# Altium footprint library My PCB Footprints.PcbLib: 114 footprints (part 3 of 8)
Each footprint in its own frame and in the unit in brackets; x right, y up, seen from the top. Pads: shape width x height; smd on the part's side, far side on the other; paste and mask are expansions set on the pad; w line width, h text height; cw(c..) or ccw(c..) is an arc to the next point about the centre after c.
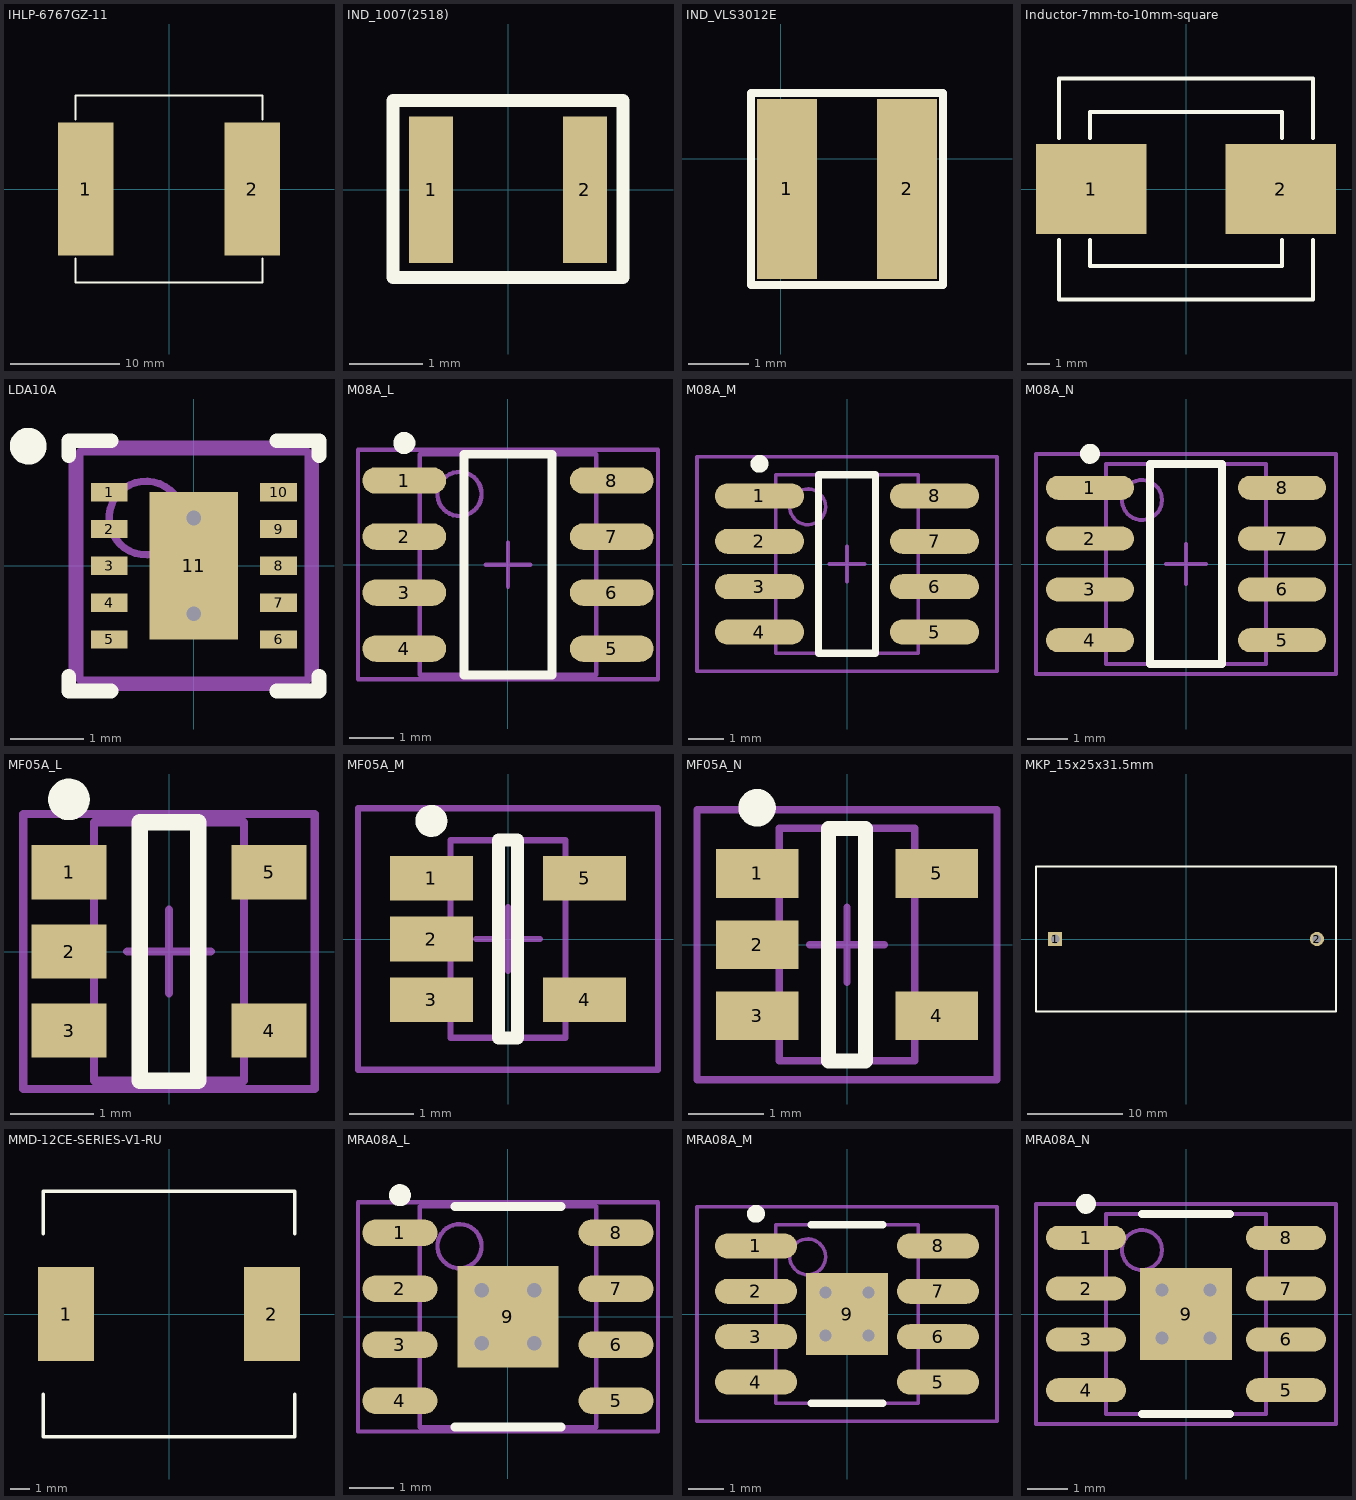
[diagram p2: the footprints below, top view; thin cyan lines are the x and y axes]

## IHLP-6767GZ-11 [mil] "Vishay Dale land pattern with wider pad.  Document 34282 rev 30-Aug-10"
height 276
pads (2):
  rect 200x480 smd: 1(-301,0) 2(301,0)
Top Overlay:
  lines w7: -337.5,-250 -337.5,-337.5 0,-337.5 ; -337.5,250 -337.5,337.5 0,337.5 337.5,337.5 337.5,250 ; 0,-337.3 337.5,-337.5 337.5,-250
Mechanical 5:
  text ".Designator" at -60,-20 h40
3D body: height 276, standoff 0, extent -337.5,-337.31 337.5,337.5

## IND_1007(2518) [mm] "Footprint for 1007 (2518 metric) inductor, Taiyo Yuden BRC2518T series"
height 1.8
pads (2):
  rect 0.6x2 smd: 1(-1.05,0) 2(1.05,0)
Top Overlay:
  lines w0.178: -1.575,-1.2 1.575,-1.2 1.575,1.225 -1.575,1.225 -1.575,-1.2
Mechanical 5:
  text ".Designator" at -0.1,-0.1 h1.02
3D body: height 1.8, standoff 0, extent -1.6,-1.225 1.6,1.2

## IND_VLS3012E [mm] "TDK VLS3012E Type Inductor footprint"
height 1.2
pads (2):
  rect 1x3 smd: 1(0.1,-0.5) 2(2.1,-0.5)
Top Overlay:
  lines w0.127: -0.5,-2.1 -0.5,1.1 2.7,1.1 2.7,-2.1 -0.5,-2.1
Mechanical 5:
  text ".Designator" at -1.524,-0.508 h1.02
3D body: height 1.2, standoff 0, extent -0.7,-2.1 2.7,1.2

## Inductor-7mm-to-10mm-square [mm] "Custom land pattern"
height 3
pads (2):
  rect 5x4.1 smd: 1(-4.3,0) 2(4.3,0)
Top Overlay:
  lines w0.178: -5.75,-2.3 -5.75,-5 0,-5 5.75,-5 5.75,-2.3 ; -5.75,2.3 -5.75,5 0,5 5.75,5 5.75,2.3 ; -4.35,-2.3 -4.35,-3.5 4.35,-3.5 4.35,-2.3 ; -4.35,2.3 -4.35,3.5 4.35,3.5 4.35,2.3
Mechanical 5:
  text ".Designator" at -1.524,-0.508 h1.02
3D body: height 3, standoff 0, extent -5.75,-5 5.75,5

## LDA10A [mm] "PSON, 10-Leads, Body 3x3mm, Pitch 0.5mm, NSC Recommended"
height 0.8
pads (11):
  rect 0.5x0.25 smd paste-0.125 mask+0.051: 1(-1.15,1) 2(-1.15,0.5) 3(-1.15,0) 4(-1.15,-0.5) 5(-1.15,-1) 6(1.15,-1) 7(1.15,-0.5) 8(1.15,0) 9(1.15,0.5) 10(1.15,1)
  rect 1.2x2 smd paste-0.6 mask+0.051: 11(0,0)
via 0,-0.65 diameter 0.5 hole 0.2
via 0,0.65 diameter 0.5 hole 0.2
Top Overlay:
  circle w0.25: c-2.25,1.625 r0.125
  lines w0.2: -1.7,-1.5 -1.7,-1.7 -1.125,-1.7 ; -1.7,1.5 -1.7,1.7 -1.125,1.7 ; 1.125,-1.7 1.7,-1.7 1.7,-1.5 ; 1.125,1.7 1.7,1.7 1.7,1.5
Top Paste:
  region: 1.5,-0.875 1,-0.875 1,-1.125 1.5,-1.125
  region: 1.5,-0.375 1,-0.375 1,-0.625 1.5,-0.625
  region: 1.5,0.125 1,0.125 1,-0.125 1.5,-0.125
  region: 1.5,0.625 1,0.625 1,0.375 1.5,0.375
  region: 1.5,1.125 1,1.125 1,0.875 1.5,0.875
  rectangle: -1.5,-1.125 -1,-0.875
  rectangle: -1.5,-0.625 -1,-0.375
  rectangle: -1.5,-0.125 -1,0.125
  rectangle: -1.5,0.375 -1,0.625
  rectangle: -1.5,0.875 -1,1.125
  rectangle: -0.57,-0.95 0.57,0.95
Mechanical 5:
  text ".Designator" at -1.524,-0.508 h1.02
Mechanical 13:
  circle w0.1: c-0.65,0.65 r0.5
  lines w0.1: -1.55,-1.55 1.55,-1.55 1.55,1.55 -1.55,1.55 -1.55,-1.55
Mechanical 15:
  lines w0.1: -0.5,0 0.5,0 ; 0,-0.5 0,0.5 ; -1.65,-1.65 1.65,-1.65 1.65,1.65 -1.65,1.65 -1.65,-1.65
3D body: height 0.8, standoff 0, extent -1.55,-1.55 1.55,1.55

## M08A_L [mm] "SOIC, 8-Leads, Body 4.9x3.9mm, Pitch 1.27mm, IPC High Density"
height 1.75
pads (8):
  oval 1.9x0.6 smd: 1(-2.35,1.905) 2(-2.35,0.635) 3(-2.35,-0.635) 4(-2.35,-1.905) 5(2.35,-1.905) 6(2.35,-0.635) 7(2.35,0.635) 8(2.35,1.905)
Top Overlay:
  circle w0.25: c-2.35,2.755 r0.125
  lines w0.2: -1,-2.5 1,-2.5 1,2.5 -1,2.5 -1,-2.5
Mechanical 5:
  text ".Designator" at -1.524,-0.508 h1.02
Mechanical 13:
  circle w0.1: c-1.1,1.6 r0.5
  lines w0.1: -2,-2.5 2,-2.5 2,2.5 -2,2.5 -2,-2.5
Mechanical 15:
  lines w0.1: -0.5,0 0.5,0 ; 0,-0.5 0,0.5 ; -3.4,-2.6 3.4,-2.6 3.4,2.6 -3.4,2.6 -3.4,-2.6
3D body: height 1.75, standoff 0, extent -2,-2.5 2,2.5

## M08A_M [mm] "SOIC, 8-Leads, Body 4.9x3.9mm, Pitch 1.27mm, IPC Low Density"
height 1.75
pads (8):
  oval 2.5x0.7 smd: 1(-2.45,1.905) 2(-2.45,0.635) 3(-2.45,-0.635) 4(-2.45,-1.905) 5(2.45,-1.905) 6(2.45,-0.635) 7(2.45,0.635) 8(2.45,1.905)
Top Overlay:
  circle w0.25: c-2.45,2.805 r0.125
  lines w0.2: -0.8,-2.5 -0.8,2.5 0.8,2.5 0.8,-2.5 -0.8,-2.5
Mechanical 5:
  text ".Designator" at -1.524,-0.508 h1.02
Mechanical 13:
  circle w0.1: c-1.1,1.6 r0.5
  lines w0.1: -2,-2.5 -2,2.5 2,2.5 2,-2.5 -2,-2.5
Mechanical 15:
  lines w0.1: -0.5,0 0.5,0 ; 0,-0.5 0,0.5 ; -4.2,-3 -4.2,3 4.2,3 4.2,-3 -4.2,-3
3D body: height 1.75, standoff 0, extent -2,-2.5 2,2.5

## M08A_N [mm] "SOIC, 8-Leads, Body 4.9x3.9mm, Pitch 1.27mm, IPC Medium Density"
height 1.75
pads (8):
  oval 2.2x0.6 smd: 1(-2.4,1.905) 2(-2.4,0.635) 3(-2.4,-0.635) 4(-2.4,-1.905) 5(2.4,-1.905) 6(2.4,-0.635) 7(2.4,0.635) 8(2.4,1.905)
Top Overlay:
  circle w0.25: c-2.4,2.755 r0.125
  lines w0.2: -0.9,-2.5 -0.9,2.5 0.9,2.5 0.9,-2.5 -0.9,-2.5
Mechanical 5:
  text ".Designator" at -1.524,-0.508 h1.02
Mechanical 13:
  circle w0.1: c-1.1,1.6 r0.5
  lines w0.1: -2,-2.5 -2,2.5 2,2.5 2,-2.5 -2,-2.5
Mechanical 15:
  lines w0.1: -0.5,0 0.5,0 ; 0,-0.5 0,0.5 ; -3.75,-2.75 -3.75,2.75 3.75,2.75 3.75,-2.75 -3.75,-2.75
3D body: height 1.75, standoff 0, extent -2,-2.5 2,2.5

## MF05A_L [mm] "SOT23, 5-Leads, Body 2.9x1.6mm, Pitch 0.95mm, Lead Span 2.8mm, IPC High Density"
height 1.19
pads (5):
  rect 0.9x0.65 smd: 1(-1.2,0.95) 2(-1.2,0) 3(-1.2,-0.95) 4(1.2,-0.95) 5(1.2,0.95)
Top Overlay:
  circle w0.25: c-1.2,1.825 r0.125
  lines w0.2: -0.35,-1.55 -0.35,1.55 0.35,1.55 0.35,-1.55 -0.35,-1.55
Mechanical 5:
  text ".Designator" at -1.524,-0.508 h1.02
Mechanical 13:
  lines w0.1: -0.9,-1.55 0.9,-1.55 0.9,1.55 -0.9,1.55 -0.9,-1.55
Mechanical 15:
  lines w0.1: -0.5,0 0.5,0 ; 0,-0.5 0,0.5 ; -1.75,-1.65 1.75,-1.65 1.75,1.65 -1.75,1.65 -1.75,-1.65
3D body: height 1.19, standoff 0, extent -0.9,-1.55 0.9,1.55

## MF05A_M [mm] "SOT23, 5-Leads, Body 2.9x1.6mm, Pitch 0.95mm, Lead Span 2.8mm, IPC Low Density"
height 1.19
pads (5):
  rect 1.3x0.7 smd: 1(-1.2,0.95) 2(-1.2,0) 3(-1.2,-0.95) 4(1.2,-0.95) 5(1.2,0.95)
Top Overlay:
  circle w0.25: c-1.2,1.85 r0.125
  lines w0.2: -0.15,-1.55 -0.15,1.55 0.15,1.55 0.15,-1.55 -0.15,-1.55
Mechanical 5:
  text ".Designator" at -1.524,-0.508 h1.02
Mechanical 13:
  lines w0.1: -0.9,-1.55 0.9,-1.55 0.9,1.55 -0.9,1.55 -0.9,-1.55
Mechanical 15:
  lines w0.1: -0.5,0 0.5,0 ; 0,-0.5 0,0.5 ; -2.35,-2.05 2.35,-2.05 2.35,2.05 -2.35,2.05 -2.35,-2.05
3D body: height 1.19, standoff 0, extent -0.9,-1.55 0.9,1.55

## MF05A_N [mm] "SOT23, 5-Leads, Body 2.9x1.6mm, Pitch 0.95mm, Lead Span 2.8mm, IPC Medium Density"
height 1.19
pads (5):
  rect 1.1x0.65 smd: 1(-1.2,0.95) 2(-1.2,0) 3(-1.2,-0.95) 4(1.2,-0.95) 5(1.2,0.95)
Top Overlay:
  circle w0.25: c-1.2,1.825 r0.125
  lines w0.2: -0.25,-1.55 -0.25,1.55 0.25,1.55 0.25,-1.55 -0.25,-1.55
Mechanical 5:
  text ".Designator" at -1.524,-0.508 h1.02
Mechanical 13:
  lines w0.1: -0.9,-1.55 0.9,-1.55 0.9,1.55 -0.9,1.55 -0.9,-1.55
Mechanical 15:
  lines w0.1: -0.5,0 0.5,0 ; 0,-0.5 0,0.5 ; -2,-1.8 2,-1.8 2,1.8 -2,1.8 -2,-1.8
3D body: height 1.19, standoff 0, extent -0.9,-1.55 0.9,1.55

## MKP_15x25x31.5mm [mm] "Flm capacitors, 27.5mm spacing"
height 24.5
pads (2):
  rect 1.5x1.5 hole 0.9: 1(-13.75,0)
  round 1.5 hole 0.9: 2(13.75,0)
Top Overlay:
  lines w0.178: -15.75,-7.62 0.62,-7.62 15.75,-7.62 15.75,0 15.75,7.62 -0.396,7.62 -15.75,7.62 -15.75,0 -15.75,-7.62
Mechanical 5:
  text ".Designator" at -1.524,-0.508 h1.02
3D body: height 24.5, standoff 0, extent -15.749,-7.62 15.749,7.366

## MMD-12CE-SERIES-V1-RU [mm] "Mag.Layers land pattern"
height 3.5
pads (2):
  rect 2.95x4.95 smd: 1(-5.4,0) 2(5.4,0)
Top Overlay:
  lines w0.178: -6.6,-4.2 -6.6,-6.45 0,-6.45 6.6,-6.45 6.6,-4.2 ; -6.6,4.2 -6.6,6.45 0,6.45 6.6,6.45 6.6,4.2
Mechanical 5:
  text ".Designator" at -1.524,-0.508 h1.02
3D body: height 3.5, standoff 0, extent -6.6,-6.45 6.6,6.45

## MRA08A_L [mm] "SOIC, 8-Leads, Body 4.9x3.9mm, Pitch 1.27mm, Exposed Pad, IPC High Density"
height 1.68
pads (9):
  oval 1.7x0.6 smd: 1(-2.45,1.905) 2(-2.45,0.635) 3(-2.45,-0.635) 4(-2.45,-1.905) 5(2.45,-1.905) 6(2.45,-0.635) 7(2.45,0.635) 8(2.45,1.905)
  rect 2.29x2.29 smd: 9(0,0)
via -0.6,-0.6 diameter 0.66 hole 0.33
via 0.6,-0.6 diameter 0.66 hole 0.33
via 0.6,0.6 diameter 0.66 hole 0.33
via -0.6,0.6 diameter 0.66 hole 0.33
Top Overlay:
  circle w0.25: c-2.45,2.755 r0.125
  lines w0.2: -1.2,-2.5 1.2,-2.5 ; -1.2,2.5 1.2,2.5 ; -1.1,2.5 1.1,2.5
Mechanical 5:
  text ".Designator" at -1.524,-0.508 h1.02
Mechanical 13:
  circle w0.1: c-1.1,1.6 r0.5
  lines w0.1: -2,-2.5 -2,2.5 2,2.5 2,-2.5 -2,-2.5
Mechanical 15:
  lines w0.1: -3.4,-2.6 -3.4,2.6 3.4,2.6 3.4,-2.6 -3.4,-2.6 ; -0.5,0 0.5,0 -0.5,0 ; 0,-0.5 0,0.5 0,-0.5
3D body: height 1.68, standoff 0.03, extent -2,-2.5 2,2.5

## MRA08A_M [mm] "SOIC, 8-Leads, Body 4.9x3.9mm, Pitch 1.27mm, Exposed Pad, IPC Low Density"
height 1.68
pads (9):
  oval 2.3x0.7 smd: 1(-2.55,1.905) 2(-2.55,0.635) 3(-2.55,-0.635) 4(-2.55,-1.905) 5(2.55,-1.905) 6(2.55,-0.635) 7(2.55,0.635) 8(2.55,1.905)
  rect 2.29x2.29 smd: 9(0,0)
via -0.6,-0.6 diameter 0.66 hole 0.33
via 0.6,-0.6 diameter 0.66 hole 0.33
via 0.6,0.6 diameter 0.66 hole 0.33
via -0.6,0.6 diameter 0.66 hole 0.33
Top Overlay:
  circle w0.25: c-2.55,2.805 r0.125
  lines w0.2: -1,-2.5 1,-2.5 ; -1,2.5 1,2.5 -1,2.5
Mechanical 5:
  text ".Designator" at -1.524,-0.508 h1.02
Mechanical 13:
  circle w0.1: c-1.1,1.6 r0.5
  lines w0.1: -2,-2.5 -2,2.5 2,2.5 2,-2.5 -2,-2.5
Mechanical 15:
  lines w0.1: -4.2,-3 -4.2,3 4.2,3 4.2,-3 -4.2,-3 ; -0.5,0 0.5,0 -0.5,0 ; 0,-0.5 0,0.5 0,-0.5
3D body: height 1.68, standoff 0.03, extent -2,-2.5 2,2.5

## MRA08A_N [mm] "SOIC, 8-Leads, Body 4.9x3.9mm, Pitch 1.27mm, Exposed Pad, IPC Medium Density"
height 1.68
pads (9):
  oval 2x0.6 smd: 1(-2.5,1.905) 2(-2.5,0.635) 3(-2.5,-0.635) 4(-2.5,-1.905) 5(2.5,-1.905) 6(2.5,-0.635) 7(2.5,0.635) 8(2.5,1.905)
  rect 2.29x2.29 smd: 9(0,0)
via -0.6,-0.6 diameter 0.66 hole 0.33
via 0.6,-0.6 diameter 0.66 hole 0.33
via 0.6,0.6 diameter 0.66 hole 0.33
via -0.6,0.6 diameter 0.66 hole 0.33
Top Overlay:
  circle w0.25: c-2.5,2.755 r0.125
  lines w0.2: -1.1,-2.5 1.1,-2.5 ; -1.1,2.5 1.1,2.5
Mechanical 5:
  text ".Designator" at -1.524,-0.508 h1.02
Mechanical 13:
  circle w0.1: c-1.1,1.6 r0.5
  lines w0.1: -2,-2.5 2,-2.5 2,2.5 -2,2.5 -2,-2.5
Mechanical 15:
  lines w0.1: -0.5,0 0.5,0 ; 0,-0.5 0,0.5 ; -3.75,-2.75 3.75,-2.75 3.75,2.75 -3.75,2.75 -3.75,-2.75
3D body: height 1.68, standoff 0.03, extent -2,-2.5 2,2.5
